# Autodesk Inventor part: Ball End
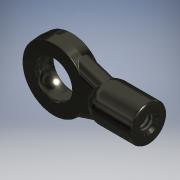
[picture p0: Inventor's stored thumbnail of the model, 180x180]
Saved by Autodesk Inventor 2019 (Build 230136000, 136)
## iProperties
Shininess: 50.0
Compacted: True
Length Units: 11272
Angle Units: 11279
Time Units: 11290
Mass Units: 11286
Length Display Precision: 4
Angle Display Precision: 2
Company: Autodesk
Created: 2000-03
Part Number: Ball End
Project: Inventor Samples
User Status: IN PROGRESS
Document SubType Name: Modeling
Designer: Autodesk, Inc.
Density: 1.38 g/cm^3
Mass: 0.467497 g
Surface Area: 4.55394 cm^2
Volume: 0.338766 cm^3
Material: Phenolic
Appearance: Gunmetal
Density: 0.0
Volumn: 0.0
Area: 0.0
PropertySet Name: Model Information
Control State: 0
Master: False
Checked Out: False
Checked Out Date: 2018-05-30
Last Check In Date: 2018-05-30
Author: Autodesk, Inc.
Revision Number: A
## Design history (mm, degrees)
node "Extrusion1" dims "d1" = 2.921, "d2" = 0
  sketch "Sketch2"
    geometry: C1 r 5.08 at (-4.835, 0.428)
    constraints: 1 centre point
    dimensions: "d0" = 10.16 diameter of C1
node "Revolution1" dims "d5" = 90 deg
  sketch "Sketch3"
    geometry: L1 (8.818, 3.286)-(3.103, 3.286); L2 (0.245, 0.428)-(8.818, 0.428); L3 (8.818, 0.428)-(8.818, 3.286); A1 r 2.858 centre (3.103, 0.428) between (3.103, 3.286) and (0.245, 0.428); 1 further point
    constraints: 6 end point, 2 horizontal alignment, 2 point on circle, 1 centre point, 1 horizontal, 1 parallel, 1 perpendicular, 1 point on line, 1 tangent, 1 other
    dimensions: "d3" = 5.715 diameter of L1 L2; "d4" = 5.715 distance from line of L3 A1.centre
node "Extrusion2" dims "d10" = 2.921 (= d1), "d11" = 0
  sketch "Sketch4"
    geometry: L1 (-1.71, -3.577)-(5.227, -1.318); L2 (5.227, -1.318)-(5.227, 2.175); L3 (5.227, 2.175)-(-1.71, 4.434); A1 r 5.08 centre (-4.835, 0.428) between (-1.71, -3.577) and (-1.71, 4.434) reference; 1 further point
    constraints: 6 end point, 2 point on circle, 1 midpoint, 1 vertical, 1 vertical alignment
    dimensions: "d6" = 3.4925 distance of L1.end L2.end; "d8" = 30 deg dimension on point (5.227, 0.428) A1.centre L1.start; "d9" = 60 deg dimension on point (5.227, 0.428) L3.end L1.start (= 2 x d8)
node "Fillet1" dims "d12" = 1.27
node "Split1"
node "Hole1" dims "d15" = 2.15646, "d16" = 9.525, "d17" = 6.35, "d18" = 60 deg, "d19" = 5.715, "d20" = 118 deg
  sketch "Sketch5"
    geometry: C1 r 2.857 at (0, 0) reference
node "Fillet2" dims "d21" = 0.381
node "Fillet3" dims "d22" = 0.127
node "Fillet4" dims "d23" = 0.127
node "Chamfer1" dims "d24" = 0.381, "d25" = 0.381, "d30" = 45 deg
node "Revolution2" dims "d27" = 90 deg
  sketch "Sketch6"
    geometry: L1 (-8.01, 0.428)-(-1.66, 0.428); A1 r 5.079 centre (-4.835, 0.428) between (-1.731, 4.449) and (-1.731, -3.592) reference; A2 r 3.175 centre (-4.835, 0.428) between (-8.01, 0.428) and (-1.66, 0.428)
    constraints: 2 end point, 2 point on circle, 1 centre point, 1 coincident, 1 horizontal, 1 midpoint
    dimensions: "d26" = 3.175 radius of A2
node "Chamfer2" dims "d28" = 0.127, "d29" = 0.127, "d31" = 45 deg
body "Solid1"
node "FaceDraft1" dims "d13" = 5 deg
node "FaceDraft2" dims "d14" = 5 deg
